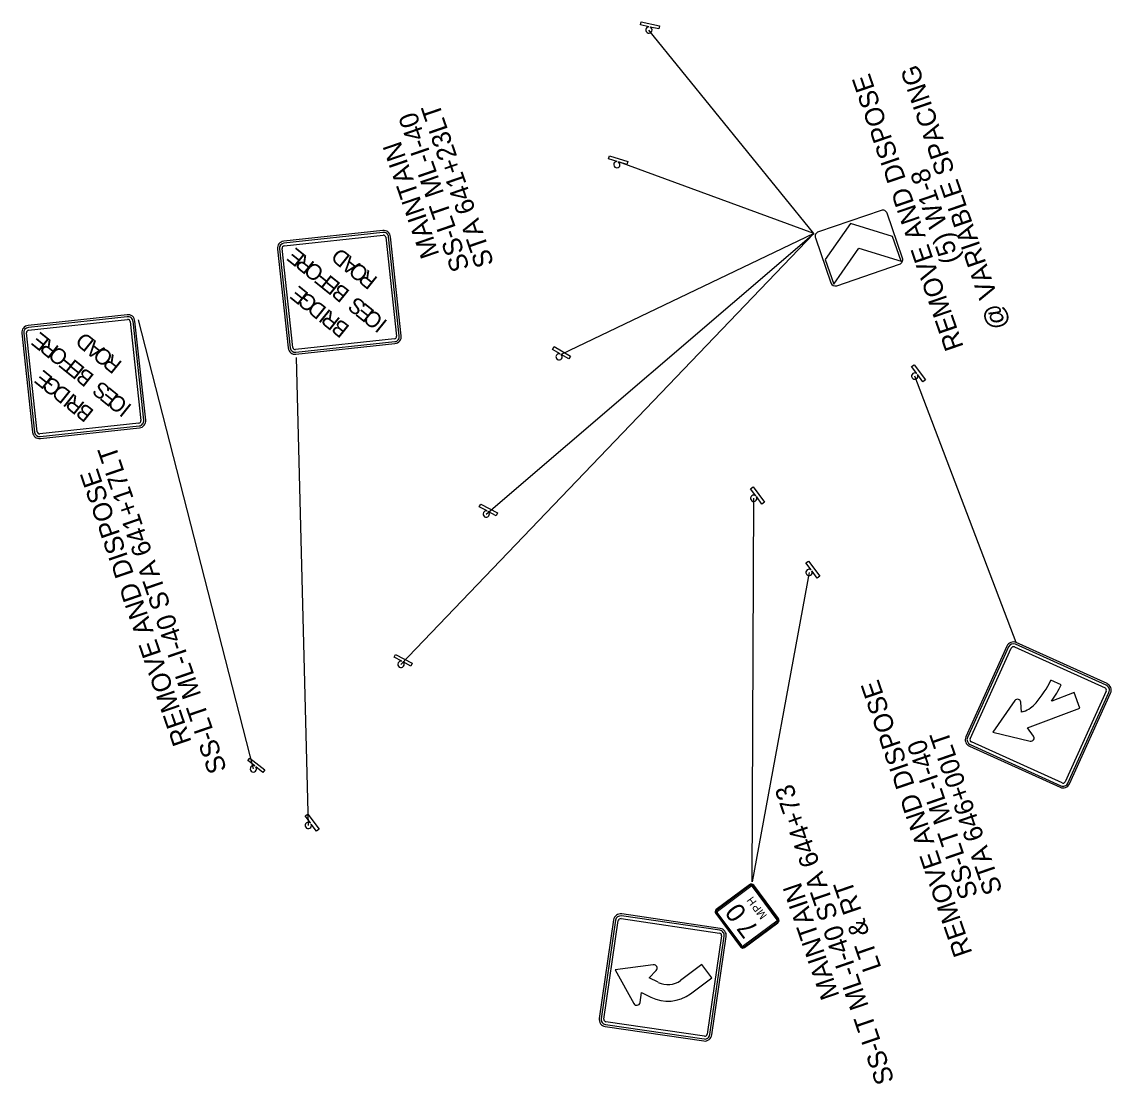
# Model space of a CAD drawing. Extents: x 641128 to 649424, y 422807 to 432853.
# Drawn here: x 644130 to 644819, y 425469 to 426141 of the extents above; entities that cross this region are included whole.
import ezdxf

# ---------------------------------------------------------------- set-up
doc = ezdxf.new("R2010")
doc.units = 0
doc.layers.add('R_Dimension_2', color=7, linetype='Continuous')
doc.layers.add('S_SIGN', color=7, linetype='Continuous')

msp = doc.modelspace()

# ---------------------------------------------------------------- linework, layer by layer
at = {"layer": 'S_SIGN'}
for p, q in [((644521.05, 426139.38), (644521.48, 426141.33)), ((644526.44, 426138.18), (644521.05, 426139.38)), ((644521.48, 426141.33), (644533.19, 426138.72)), ((644526.42, 426138.12), (644526.44, 426138.18)), ((644527.32, 426137.98), (644527.31, 426137.94)), ((644532.76, 426136.77), (644527.32, 426137.98)), ((644533.19, 426138.72), (644532.76, 426136.77)), ((644500.96, 426054.53), (644501.54, 426056.45)), ((644501.54, 426056.45), (644513.03, 426053)), ((644506.25, 426052.95), (644500.96, 426054.53)), ((644506.24, 426052.89), (644506.25, 426052.95)), ((644507.12, 426052.69), (644507.11, 426052.64)), ((644630.8, 426007.37), (644507.11, 426052.64)), ((644512.46, 426051.09), (644507.12, 426052.69)), ((644513.03, 426053), (644512.46, 426051.09)), ((644673.36, 426021.99), (644633.64, 426008.34)), ((644653.98, 426013.75), (644638.06, 425990.83)), ((644680.62, 426005.45), (644653.98, 426013.75)), ((644686.92, 425991.75), (644677.17, 426020.12)), ((644358, 426009.26), (644295.36, 426002.48)), ((644369.45, 425734.67), (644630.8, 426007.37)), ((644423.49, 425829.79), (644630.8, 426007.37)), ((644630.8, 426007.37), (644470.98, 425930.79)), ((644369.74, 425942.64), (644362.96, 426005.27)), ((644631.77, 426004.53), (644641.52, 425976.16)), ((644291.38, 425997.52), (644298.16, 425934.88)), ((644643.42, 425975.23), (644659.34, 425998.14)), ((644659.34, 425998.14), (644685.98, 425989.84)), ((644645.33, 425974.3), (644685.05, 425987.94)), ((644196.27, 425955.93), (644133.64, 425949.14)), ((644208.02, 425889.3), (644201.23, 425951.94)), ((644203.25, 425952.62), (644276.07, 425668.52)), ((644129.65, 425944.18), (644136.43, 425881.55)), ((644303.12, 425930.89), (644365.75, 425937.68)), ((644465.42, 425934.01), (644466.42, 425935.74)), ((644470.19, 425931.24), (644465.42, 425934.01)), ((644466.42, 425935.74), (644476.8, 425929.73)), ((644470.16, 425931.19), (644470.19, 425931.24)), ((644303.24, 425928.81), (644310.93, 425632.71)), ((644470.98, 425930.79), (644470.95, 425930.75)), ((644475.8, 425928), (644470.98, 425930.79)), ((644476.8, 425929.73), (644475.8, 425928)), ((644692.67, 425923.11), (644694.27, 425924.31)), ((644694.27, 425924.31), (644701.44, 425914.68)), ((644695.97, 425918.68), (644692.67, 425923.11)), ((644695.92, 425918.65), (644695.97, 425918.68)), ((644696.51, 425917.96), (644696.47, 425917.93)), ((644699.84, 425913.49), (644696.51, 425917.96)), ((644701.44, 425914.68), (644699.84, 425913.49)), ((644141.39, 425877.56), (644204.03, 425884.35)), ((644590.78, 425845.78), (644592.38, 425846.97)), ((644594.08, 425841.35), (644590.78, 425845.78)), ((644592.38, 425846.97), (644599.55, 425837.35)), ((644594.03, 425841.32), (644594.08, 425841.35)), ((644419.12, 425834.36), (644420.06, 425836.13)), ((644424, 425831.78), (644419.12, 425834.36)), ((644420.06, 425836.13), (644430.67, 425830.52)), ((644591.79, 425596.96), (644592.76, 425839.77)), ((644594.62, 425840.62), (644594.58, 425840.6)), ((644597.95, 425836.15), (644594.62, 425840.62)), ((644599.55, 425837.35), (644597.95, 425836.15)), ((644423.98, 425831.73), (644424, 425831.78)), ((644424.81, 425831.36), (644424.78, 425831.32)), ((644429.73, 425828.75), (644424.81, 425831.36)), ((644430.67, 425830.52), (644429.73, 425828.75)), ((644625.8, 425798.88), (644627.4, 425800.07)), ((644627.4, 425800.07), (644634.57, 425790.45)), ((644629.1, 425794.45), (644625.8, 425798.88)), ((644629.05, 425794.42), (644629.1, 425794.45)), ((644629.64, 425793.72), (644629.6, 425793.7)), ((644632.97, 425789.25), (644629.64, 425793.72)), ((644627.78, 425792.87), (644591.79, 425596.96)), ((644634.57, 425790.45), (644632.97, 425789.25)), ((644752.96, 425746.19), (644726.98, 425688.79)), ((644816.31, 425722.45), (644758.91, 425748.43)), ((644365.16, 425739.23), (644366.09, 425741)), ((644370.04, 425736.65), (644365.16, 425739.23)), ((644366.09, 425741), (644376.7, 425735.39)), ((644370.01, 425736.6), (644370.04, 425736.65)), ((644370.84, 425736.23), (644370.82, 425736.18)), ((644375.77, 425733.62), (644370.84, 425736.23)), ((644376.7, 425735.39), (644375.77, 425733.62)), ((644787.3, 425721.79), (644780.81, 425724.73)), ((644757.99, 425711.72), (644743.99, 425691.8)), ((644762.29, 425704.31), (644761.73, 425710.71)), ((644795.48, 425716.81), (644781.28, 425711.46)), ((644792.57, 425659.1), (644818.55, 425716.49)), ((644799.18, 425706.99), (644795.48, 425716.81)), ((644763.54, 425704.78), (644762.29, 425704.31)), ((644765.99, 425694.48), (644799.18, 425706.99)), ((644743.99, 425691.8), (644767.65, 425686.07)), ((644769.8, 425689.3), (644765.99, 425694.48)), ((644729.22, 425682.84), (644786.62, 425656.86)), ((644272.73, 425673.81), (644273.98, 425675.37)), ((644277.03, 425670.35), (644272.73, 425673.81)), ((644273.98, 425675.37), (644283.33, 425667.85)), ((644276.99, 425670.31), (644277.03, 425670.35)), ((644277.73, 425669.78), (644277.7, 425669.75)), ((644282.08, 425666.29), (644277.73, 425669.78)), ((644283.33, 425667.85), (644282.08, 425666.29)), ((644308.94, 425638.72), (644310.55, 425639.91)), ((644312.25, 425634.29), (644308.94, 425638.72)), ((644310.55, 425639.91), (644317.73, 425630.3)), ((644312.2, 425634.26), (644312.25, 425634.29)), ((644312.79, 425633.57), (644312.75, 425633.54)), ((644316.12, 425629.1), (644312.79, 425633.57)), ((644317.73, 425630.3), (644316.12, 425629.1)), ((644590.12, 425595.23), (644569.07, 425579.55)), ((644608.42, 425573.79), (644592.74, 425594.84)), ((644504.11, 425572.9), (644495, 425510.56)), ((644571.55, 425567.58), (644509.22, 425576.7)), ((644568.68, 425576.92), (644584.36, 425555.87)), ((644586.99, 425555.49), (644608.04, 425571.17)), ((644566.24, 425500.14), (644575.36, 425562.48)), ((644529.22, 425544.52), (644505.13, 425541.27)), ((644505.13, 425541.27), (644516.84, 425519.96)), ((644526.52, 425536.36), (644531.02, 425540.92)), ((644559.96, 425544.7), (644546.48, 425534.65)), ((644566.23, 425536.27), (644559.96, 425544.7)), ((644532.34, 425533.43), (644526.52, 425536.36)), ((644552.76, 425526.23), (644566.23, 425536.27)), ((644520.8, 425520.66), (644521.79, 425526.99)), ((644521.79, 425526.99), (644527.61, 425524.05)), ((644498.8, 425505.46), (644561.14, 425496.34))]:
    msp.add_line(p, q, dxfattribs=at)
for points in [[(644630.8, 426007.37), (644526.47, 426136.12)], [(644638.06, 425990.83), (644643.42, 425975.23), (644659.34, 425998.14), (644685.98, 425989.84), (644680.62, 426005.45), (644653.98, 426013.75), (644638.06, 425990.83)], [(644358.13, 426008.02), (644295.5, 426001.23)], [(644358.13, 426008.02), (644358.13, 426008.02), (644358.13, 426008.02)], [(644295.69, 425999.49), (644358.32, 426006.28)], [(644359.97, 426004.95), (644366.76, 425942.32)], [(644368.5, 425942.51), (644361.71, 426005.14)], [(644292.62, 425997.65), (644299.4, 425935.02)], [(644292.62, 425997.65), (644292.62, 425997.65), (644292.62, 425997.65)], [(644301.15, 425935.21), (644294.36, 425997.84)], [(644196.4, 425954.68), (644133.77, 425947.9)], [(644133.96, 425946.16), (644196.59, 425952.94)], [(644196.4, 425954.68), (644196.4, 425954.68), (644196.4, 425954.68)], [(644198.25, 425951.61), (644205.03, 425888.98)], [(644206.77, 425889.17), (644199.99, 425951.8)], [(644130.89, 425944.32), (644137.68, 425881.68)], [(644130.89, 425944.32), (644130.89, 425944.32), (644130.89, 425944.32)], [(644139.42, 425881.87), (644132.63, 425944.51)], [(644365.43, 425940.66), (644302.8, 425933.88)], [(644302.99, 425932.14), (644365.62, 425938.92)], [(644368.5, 425942.51), (644368.5, 425942.51), (644368.5, 425942.51)], [(644302.99, 425932.14), (644302.99, 425932.14), (644302.99, 425932.14)], [(644758.91, 425748.43), (644694.65, 425917.11)], [(644203.7, 425887.33), (644141.07, 425880.54)], [(644141.26, 425878.8), (644203.89, 425885.59)], [(644206.77, 425889.17), (644206.77, 425889.17), (644206.77, 425889.17)], [(644141.26, 425878.8), (644141.26, 425878.8), (644141.26, 425878.8)], [(644753.98, 425745.72), (644728, 425688.33)], [(644729.71, 425687.55), (644755.69, 425744.95)], [(644753.98, 425745.72), (644753.98, 425745.72), (644753.98, 425745.72)], [(644757.68, 425745.7), (644815.07, 425719.71)], [(644815.84, 425721.42), (644758.45, 425747.4)], [(644815.82, 425717.73), (644789.84, 425660.34)], [(644815.84, 425721.42), (644815.84, 425721.42), (644815.84, 425721.42)], [(644791.55, 425659.56), (644817.53, 425716.96)], [(644729.69, 425683.86), (644787.08, 425657.88)], [(644729.69, 425683.86), (644729.69, 425683.86), (644729.69, 425683.86)], [(644787.85, 425659.59), (644730.46, 425685.57)], [(644791.55, 425659.56), (644791.55, 425659.56), (644791.55, 425659.56)], [(644590.42, 425594.83), (644569.36, 425579.15)], [(644569.81, 425578.55), (644590.86, 425594.23)], [(644590.42, 425594.83), (644590.42, 425594.83), (644590.42, 425594.83)], [(644591.74, 425594.1), (644607.42, 425573.05)], [(644608.02, 425573.49), (644592.34, 425594.55)], [(644505.35, 425572.72), (644496.24, 425510.38)], [(644497.97, 425510.13), (644507.08, 425572.46)], [(644505.35, 425572.72), (644505.35, 425572.72), (644505.35, 425572.72)], [(644508.78, 425573.73), (644571.12, 425564.62)], [(644571.37, 425566.35), (644509.04, 425575.46)], [(644569.08, 425577.22), (644584.76, 425556.17)], [(644569.08, 425577.22), (644569.08, 425577.22), (644569.08, 425577.22)], [(644585.36, 425556.62), (644569.68, 425577.67)], [(644608.02, 425573.49), (644608.02, 425573.49), (644608.02, 425573.49)], [(644571.37, 425566.35), (644571.37, 425566.35), (644571.37, 425566.35)], [(644607.29, 425572.17), (644586.24, 425556.49)], [(644586.69, 425555.89), (644607.74, 425571.57)], [(644572.39, 425562.91), (644563.27, 425500.58)], [(644565, 425500.32), (644574.12, 425562.66)], [(644586.69, 425555.89), (644586.69, 425555.89), (644586.69, 425555.89)], [(644498.98, 425506.69), (644561.32, 425497.58)], [(644498.98, 425506.69), (644498.98, 425506.69), (644498.98, 425506.69)], [(644561.57, 425499.31), (644499.23, 425508.43)], [(644565, 425500.32), (644565, 425500.32), (644565, 425500.32)]]:
    msp.add_lwpolyline(points, dxfattribs=at)
for centre, radius, start, end in [((644526.47, 426136.12), 2, 167.43548, 65.11558), ((644526.47, 426136.12), 2, 91.29761, 167.43548), ((644506.14, 426050.89), 2, 163.32421, 61.0043), ((644506.14, 426050.89), 2, 87.18633, 163.32421), ((644674.33, 426019.15), 3, 18.95524, 108.95545), ((644358.48, 426004.79), 4.5, 6.18416, 96.18437), ((644358.48, 426004.79), 3.25, 6.18416, 96.18437), ((644634.61, 426005.51), 3, 108.95518, 198.95539), ((644295.85, 425998), 4.5, 96.18437, 186.18401), ((644295.85, 425998), 3.25, 96.18437, 186.18401), ((644358.48, 426004.79), 1.5, 6.18416, 96.18437), ((644295.85, 425998), 1.5, 96.18437, 186.18401), ((644684.08, 425990.78), 3, 288.95503, 18.95524), ((644644.36, 425977.13), 3, 198.95539, 288.95503), ((644196.75, 425951.45), 4.5, 6.18416, 96.18437), ((644196.75, 425951.45), 3.25, 6.18416, 96.18437), ((644196.75, 425951.45), 1.5, 6.18416, 96.18437), ((644134.12, 425944.67), 4.5, 96.18437, 186.18401), ((644134.12, 425944.67), 3.25, 96.18437, 186.18401), ((644134.12, 425944.67), 1.5, 96.18437, 186.18401), ((644365.27, 425942.16), 1.5, 276.18395, 6.18416), ((644365.27, 425942.16), 3.25, 276.18395, 6.18416), ((644365.27, 425942.16), 4.5, 276.18395, 6.18416), ((644302.64, 425935.37), 4.5, 186.1842, 276.18395), ((644302.64, 425935.37), 3.25, 186.1842, 276.18395), ((644302.64, 425935.37), 1.5, 186.1842, 276.18395), ((644469.6, 425929.27), 2, 73.77624, 149.91412), ((644469.6, 425929.27), 2, 149.91412, 47.59421), ((644694.65, 425917.11), 2, 126.68087, 24.36096), ((644694.65, 425917.11), 2, 50.54299, 126.68087), ((644203.54, 425888.82), 1.5, 276.18395, 6.18416), ((644203.54, 425888.82), 3.25, 276.18395, 6.18416), ((644203.54, 425888.82), 4.5, 276.18395, 6.18416), ((644140.91, 425882.03), 4.5, 186.1842, 276.18395), ((644140.91, 425882.03), 3.25, 186.1842, 276.18395), ((644140.91, 425882.03), 1.5, 186.1842, 276.18395), ((644592.76, 425839.77), 2, 126.68087, 24.36096), ((644592.76, 425839.77), 2, 50.54299, 126.68087), ((644423.49, 425829.79), 2, 152.13169, 49.81179), ((644423.49, 425829.79), 2, 75.99382, 152.13169), ((644627.78, 425792.87), 2, 126.68087, 24.36096), ((644627.78, 425792.87), 2, 50.54299, 126.68087), ((644757.06, 425744.33), 4.5, 65.64457, 155.64421), ((644757.06, 425744.33), 3.38, 65.64457, 155.64421), ((644757.06, 425744.33), 1.5, 65.64457, 155.64421), ((644369.53, 425734.66), 2, 152.13169, 49.81179), ((644369.53, 425734.66), 2, 75.99382, 152.13169), ((644720.02, 425754.08), 67.5, 319.55857, 334.22343), ((644720.02, 425754.08), 74.62, 325.16955, 334.35922), ((644814.45, 425718.35), 1.5, 335.64436, 65.64457), ((644814.45, 425718.35), 3.38, 335.64436, 65.64457), ((644814.45, 425718.35), 4.5, 335.64436, 65.64457), ((644759.67, 425710.53), 2.06, 4.99584, 144.90354), ((644756.51, 425723.14), 19.66, 290.97543, 319.2274), ((644731.08, 425686.94), 4.5, 155.6444, 245.64415), ((644731.08, 425686.94), 3.38, 155.6444, 245.64415), ((644731.08, 425686.94), 1.5, 155.6444, 245.64415), ((644768.14, 425688.08), 2.06, 256.38482, 36.29309), ((644276.15, 425668.49), 2, 141.1821, 38.86219), ((644276.15, 425668.49), 2, 65.04422, 141.1821), ((644788.47, 425660.95), 4.5, 245.64415, 335.64436), ((644788.47, 425660.95), 3.38, 245.64415, 335.64436), ((644788.47, 425660.95), 1.5, 245.64415, 335.64436), ((644310.93, 425632.71), 2, 50.61848, 126.75635), ((644310.93, 425632.71), 2, 126.75635, 24.43645), ((644591.24, 425593.72), 1.87, 36.68092, 126.68113), ((644591.24, 425593.72), 1.37, 36.68092, 126.68113), ((644591.24, 425593.72), 0.625, 36.68092, 126.68113), ((644570.19, 425578.04), 1.87, 126.68087, 216.68108), ((644508.57, 425572.25), 4.5, 81.68103, 171.68067), ((644508.57, 425572.25), 3.25, 81.68103, 171.68067), ((644508.57, 425572.25), 1.5, 81.68103, 171.68067), ((644570.19, 425578.04), 1.37, 126.68087, 216.68108), ((644570.19, 425578.04), 0.625, 126.68087, 216.68108), ((644606.92, 425572.67), 0.625, 306.68071, 36.68092), ((644606.92, 425572.67), 1.37, 306.68071, 36.68092), ((644606.92, 425572.67), 1.87, 306.68071, 36.68092), ((644570.9, 425563.13), 3.25, 351.68082, 81.68103), ((644570.9, 425563.13), 4.5, 351.68082, 81.68103), ((644570.9, 425563.13), 1.5, 351.68082, 81.68103), ((644585.87, 425556.99), 1.87, 216.68108, 306.68071), ((644585.87, 425556.99), 1.37, 216.68108, 306.68071), ((644585.87, 425556.99), 0.625, 216.68108, 306.68071), ((644529.51, 425542.42), 2.13, 315.40858, 97.68775), ((644538.42, 425545.48), 13.5, 243.23652, 306.68071), ((644538.42, 425545.48), 24, 243.23652, 306.68071), ((644518.7, 425520.99), 2.13, 208.78515, 351.06432), ((644499.45, 425509.91), 4.5, 171.68086, 261.68061), ((644499.45, 425509.91), 3.25, 171.68086, 261.68061), ((644499.45, 425509.91), 1.5, 171.68086, 261.68061), ((644561.79, 425500.79), 4.5, 261.68061, 351.68082), ((644561.79, 425500.79), 3.25, 261.68061, 351.68082), ((644561.79, 425500.79), 1.5, 261.68061, 351.68082)]:
    msp.add_arc(centre, radius, start, end, dxfattribs=at)

# ---------------------------------------------------------------- texts
at = {"layer": 'R_Dimension_2'}
for s, p in [('@ VARIABLE SPACING', (644753.74, 425948.73)), ('REMOVE AND DISPOSE', (644725.66, 425935.6)), ('SS-LT ML-I-40', (644413.15, 425985.59)), ('STA 641+23LT', (644428.54, 425988.24)), ('MAINTAIN', (644393.95, 425994.06)), ('(5) W1-8 ', (644723.09, 425990.52)), ('SS-LT ML-I-40 STA 641+17LT', (644259.5, 425668.03)), ('REMOVE AND DISPOSE', (644237.17, 425685.58)), ('REMOVE AND DISPOSE', (644731.22, 425552.03)), ('STA 646+00LT', (644750.32, 425591.31)), ('SS-LT ML-I-40 ', (644734.94, 425588.66)), ('SS-LT ML-I-40 STA 644+73 ', (644681.87, 425471.19)), ('MAINTAIN', (644647.11, 425524.95)), ('LT & RT', (644673.64, 425542.6))]:
    msp.add_text(s, height=12, rotation=108.95522, dxfattribs=at).set_placement(p)
at = {"layer": 'S_SIGN'}
for s, height, rotation, p in [('E', 10, 141.1842, (644309.69, 425993.29)), ('R', 10, 141.1842, (644315.52, 425988.59)), ('D', 10, 141.1842, (644338.17, 425992.84)), ('A', 10, 141.1842, (644344.24, 425987.95)), ('O', 10, 141.1842, (644321.6, 425983.7)), ('O', 10, 141.1842, (644349.95, 425983.35)), ('F', 10, 141.1842, (644326.76, 425979.55)), ('E', 10, 141.1842, (644331.92, 425975.4)), ('R', 10, 141.1842, (644355.42, 425978.96)), ('E', 10, 141.1842, (644311.69, 425969.21)), ('B', 10, 141.1842, (644337.75, 425970.71)), ('G', 10, 141.1842, (644317.58, 425964.48)), ('S', 10, 141.1842, (644348.25, 425962.27)), ('D', 10, 141.1842, (644323.15, 425960)), ('I', 10, 141.1842, (644325.87, 425957.81)), ('R', 10, 141.1842, (644331.76, 425953.07)), ('E', 10, 141.1842, (644353.4, 425958.12)), ('B', 10, 141.1842, (644337.65, 425948.33)), ('C', 10, 141.1842, (644358.93, 425953.67)), ('I', 10, 141.1842, (644361.6, 425951.53)), ('E', 10, 141.1842, (644147.96, 425939.95)), ('R', 10, 141.1842, (644153.79, 425935.26)), ('D', 10, 141.1842, (644176.44, 425939.5)), ('A', 10, 141.1842, (644182.51, 425934.61)), ('O', 10, 141.1842, (644159.87, 425930.37)), ('O', 10, 141.1842, (644188.22, 425930.02)), ('R', 10, 141.1842, (644193.69, 425925.62)), ('F', 10, 141.1842, (644165.03, 425926.22)), ('E', 10, 141.1842, (644170.19, 425922.07)), ('E', 10, 141.1842, (644149.97, 425915.88)), ('B', 10, 141.1842, (644176.02, 425917.37)), ('G', 10, 141.1842, (644155.85, 425911.14)), ('D', 10, 141.1842, (644161.42, 425906.66)), ('S', 10, 141.1842, (644186.52, 425908.93)), ('I', 10, 141.1842, (644164.14, 425904.47)), ('R', 10, 141.1842, (644170.03, 425899.73)), ('E', 10, 141.1842, (644191.68, 425904.78)), ('C', 10, 141.1842, (644197.2, 425900.34)), ('B', 10, 141.1842, (644175.92, 425895)), ('I', 10, 141.1842, (644199.87, 425898.19)), ('H', 5, 126.68087, (644594.92, 425584.38)), ('0', 12, 126.68087, (644588.83, 425577.5)), ('P', 5, 126.68087, (644597.98, 425580.28)), ('M', 5, 126.68087, (644601.4, 425575.68)), ('7', 12, 126.68087, (644596.39, 425567.35))]:
    msp.add_text(s, height=height, rotation=rotation, dxfattribs=at).set_placement(p)

doc.saveas('drawing.dxf')
